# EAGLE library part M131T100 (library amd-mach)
AMD MACH SERIES
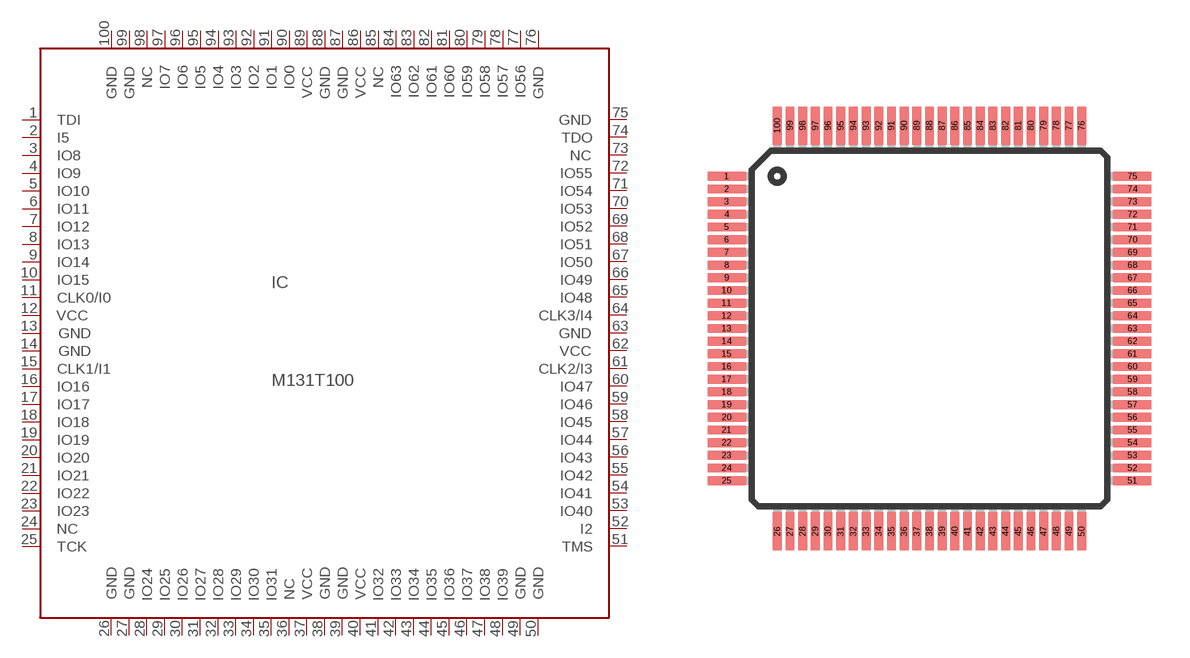
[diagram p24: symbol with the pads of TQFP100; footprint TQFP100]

Designator prefix IC

## M131T100 (OC_FARNELL: unknown; OC_NEWARK: unknown)  [TQFP100]
1  TDI  in
2  I5  in
3  IO8
4  IO9
5  IO10
6  IO11
7  IO12
8  IO13
9  IO14
10  IO15
11  CLK0/I0  in
12  VCC  pwr
13  GND  pwr
14  GND  pwr
15  CLK1/I1  in
16  IO16
17  IO17
18  IO18
19  IO19
20  IO20
21  IO21
22  IO22
23  IO23
24  NC  nc
25  TCK  in
26  GND  pwr
27  GND  pwr
28  IO24
29  IO25
30  IO26
31  IO27
32  IO28
33  IO29
34  IO30
35  IO31
36  NC1  nc
37  VCC  pwr
38  GND  pwr
39  GND  pwr
40  VCC  pwr
41  IO32
42  IO33
43  IO34
44  IO35
45  IO36
46  IO37
47  IO38
48  IO39
49  GND  pwr
50  GND  pwr
51  TMS  in
52  I2  in
53  IO40
54  IO41
55  IO42
56  IO43
57  IO44
58  IO45
59  IO46
60  IO47
61  CLK2/I3  in
62  VCC  pwr
63  GND  pwr
64  CLK3/I4  in
65  IO48
66  IO49
67  IO50
68  IO51
69  IO52
70  IO53
71  IO54
72  IO55
73  NC2  nc
74  TDO  out
75  GND  pwr
76  GND  pwr
77  IO56
78  IO57
79  IO58
80  IO59
81  IO60
82  IO61
83  IO62
84  IO63
85  NC3  nc
86  VCC  pwr
87  GND  pwr
88  GND  pwr
89  VCC  pwr
90  IO0
91  IO1
92  IO2
93  IO3
94  IO4
95  IO5
96  IO6
97  IO7
98  NC4  nc
99  GND  pwr
100  GND  pwr

## Footprint TQFP100 (pad centres in mm)
THIN QUAD FLAT PACK
smd 1.5 x 0.35: 1 -8,6; 2 -8,5.5; 3 -8,5; 4 -8,4.5; 5 -8,4; 6 -8,3.5; 7 -8,3; 8 -8,2.5; 9 -8,2; 10 -8,1.5; 11 -8,1; 12 -8,0.5; 13 -8,0; 14 -8,-0.5; 15 -8,-1; 16 -8,-1.5; 17 -8,-2; 18 -8,-2.5; 19 -8,-3; 20 -8,-3.5; 21 -8,-4; 22 -8,-4.5; 23 -8,-5; 24 -8,-5.5; 25 -8,-6; 51 8,-6; 52 8,-5.5; 53 8,-5; 54 8,-4.5; 55 8,-4; 56 8,-3.5; 57 8,-3; 58 8,-2.5; 59 8,-2; 60 8,-1.5; 61 8,-1; 62 8,-0.5; 63 8,0; 64 8,0.5; 65 8,1; 66 8,1.5; 67 8,2; 68 8,2.5; 69 8,3; 70 8,3.5; 71 8,4; 72 8,4.5; 73 8,5; 74 8,5.5; 75 8,6
smd 0.35 x 1.5: 26 -6,-8; 27 -5.5,-8; 28 -5,-8; 29 -4.5,-8; 30 -4,-8; 31 -3.5,-8; 32 -3,-8; 33 -2.5,-8; 34 -2,-8; 35 -1.5,-8; 36 -1,-8; 37 -0.5,-8; 38 0,-8; 39 0.5,-8; 40 1,-8; 41 1.5,-8; 42 2,-8; 43 2.5,-8; 44 3,-8; 45 3.5,-8; 46 4,-8; 47 4.5,-8; 48 5,-8; 49 5.5,-8; 50 6,-8; 76 6,8; 77 5.5,8; 78 5,8; 79 4.5,8; 80 4,8; 81 3.5,8; 82 3,8; 83 2.5,8; 84 2,8; 85 1.5,8; 86 1,8; 87 0.5,8; 88 0,8; 89 -0.5,8; 90 -1,8; 91 -1.5,8; 92 -2,8; 93 -2.5,8; 94 -3,8; 95 -3.5,8; 96 -4,8; 97 -4.5,8; 98 -5,8; 99 -5.5,8; 100 -6,8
